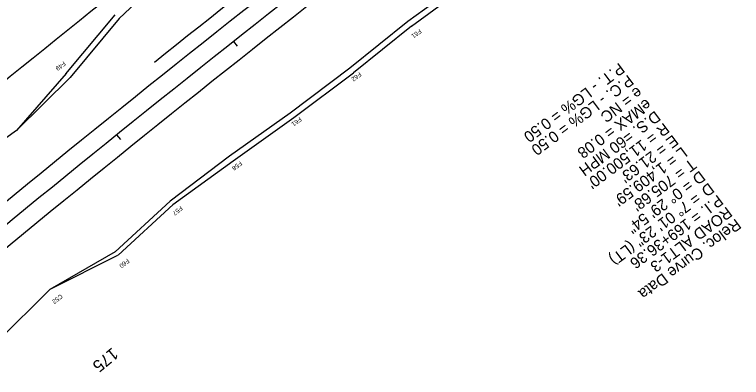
# Model space of a CAD drawing. Extents: x 1469024 to 1473560, y 1105695 to 1109739.
# Drawn here: x 1470653 to 1471138.3, y 1107228.2 to 1107470.7 of the extents above; entities that cross this region are included whole.
import ezdxf

# ---------------------------------------------------------------- set-up
doc = ezdxf.new("R2010")
doc.units = 0
for name, color, linetype in [('RD_HC_CL_Rel', 7, 'Continuous'), ('RD_HC_Data_Rel', 7, 'Continuous'), ('RD_HC_Data_Tic_Rel', 7, 'Continuous'), ('RD_HC_TX_Rel_Sta50', 7, 'Continuous'), ('RD_PD_CstnLmt', 7, 'Continuous'), ('RD_PD_CstnLmt_TX', 7, 'Continuous'), ('RD_PD_DR_ErosCtrl', 7, 'Continuous'), ('RD_PD_Final_TrvlWay', 7, 'Continuous'), ('RD_PD_GR', 7, 'Continuous'), ('RD_PD_RW', 7, 'Continuous')]:
    doc.layers.add(name, color=color, linetype=linetype)

msp = doc.modelspace()

# ---------------------------------------------------------------- linework, layer by layer
at = {"layer": 'RD_HC_CL_Rel'}
msp.add_arc((1477943.58, 1098441.09), 11500, 126.41418, 130.102414, dxfattribs=at)
at = {"layer": 'RD_HC_Data_Tic_Rel'}
for p, q in [((1470799.26, 1107452.68), (1470801.75, 1107449.55)), ((1470721.17, 1107390.22), (1470723.69, 1107387.1))]:
    msp.add_line(p, q, dxfattribs=at)
at = {"layer": 'RD_PD_CstnLmt'}
for p, q in [((1470759.49, 1107502.85), (1470722.99, 1107467.99)), ((1470955.81, 1107495.34), (1470915.62, 1107466.03)), ((1470722.99, 1107467.99), (1470690.23, 1107428.56)), ((1470915.62, 1107466.03), (1470876.9, 1107434.8)), ((1470876.9, 1107434.8), (1470837.14, 1107404.9)), ((1470690.23, 1107428.56), (1470654.32, 1107393.13)), ((1470837.14, 1107404.9), (1470796.58, 1107375.99)), ((1470654.32, 1107393.13), (1470613.1, 1107364.23)), ((1470796.58, 1107375.99), (1470756.88, 1107345.98)), ((1470756.88, 1107345.98), (1470720.21, 1107312.21)), ((1470720.21, 1107312.21), (1470676.63, 1107286.9)), ((1470676.63, 1107286.9), (1470641.02, 1107251.62))]:
    msp.add_line(p, q, dxfattribs=at)
at = {"layer": 'RD_PD_DR_ErosCtrl'}
for p, q in [((1470958.17, 1107492.11), (1470917.97, 1107462.79)), ((1470719.91, 1107470.55), (1470687.15, 1107431.12)), ((1470918.13, 1107462.91), (1470879.42, 1107431.68)), ((1470687.42, 1107431.41), (1470654.32, 1107393.13)), ((1470879.31, 1107431.6), (1470839.55, 1107401.7)), ((1470839.47, 1107401.64), (1470798.91, 1107372.73)), ((1470798.91, 1107372.73), (1470758.68, 1107343.59)), ((1470758.91, 1107343.77), (1470722.24, 1107310)), ((1470721.72, 1107309.62), (1470676.63, 1107286.9))]:
    msp.add_line(p, q, dxfattribs=at)
at = {"layer": 'RD_PD_Final_TrvlWay'}
for radius in [11512, 11488]:
    msp.add_arc((1477943.58, 1098441.09), radius, 126.41418, 130.102414, dxfattribs=at)
at = {"layer": 'RD_PD_GR'}
msp.add_arc((1477943.58, 1098441.09), 11522, 127.151906, 128.656189, dxfattribs=at)
at = {"layer": 'RD_PD_RW'}
msp.add_arc((1477943.58, 1098441.09), 11575, 126.41418, 129.547337, dxfattribs=at)

# ---------------------------------------------------------------- texts
at = {"layer": 'RD_HC_Data_Rel'}
for s, rotation, p in [('P.T. - LG% = 0.50', 216.7283, (1471056.77, 1107438.83)), ('P.C. - LG% = 0.50', 216.7283, (1471062.75, 1107430.82)), ('e = NC', 216.7283, (1471068.73, 1107422.8)), ('eMAX = 0.08', 216.7283, (1471074.71, 1107414.79)), ('D.S. =60 MPH', 216.7283, (1471080.69, 1107406.77)), ("R = 11,500.00'", 216.7689, (1471086.62, 1107398.73)), ("E = 21.63'", 216.7689, (1471092.61, 1107390.72)), ("L = 1,409.59'", 216.7689, (1471098.59, 1107382.7)), ("T = 705.68'", 216.7689, (1471104.58, 1107374.69)), ('D = 0%%d 29\' 54"', 216.7689, (1471110.57, 1107366.68)), ('D', 216.7689, (1471116.55, 1107358.67)), ('    = 7%%d 01\' 23" (LT)', 216.7689, (1471116.55, 1107358.67)), ('P.I. = 169+36.36', 216.7689, (1471122.54, 1107350.66)), ('ROAD ALT1-3', 216.7283, (1471128.53, 1107342.66)), ('Reloc. Curve Data', 216.7283, (1471134.51, 1107334.64))]:
    msp.add_text(s, height=7.5, rotation=rotation, dxfattribs=at).set_placement(p)
at = {"layer": 'RD_HC_TX_Rel_Sta50'}
msp.add_text('175', height=8, rotation=219.4035, dxfattribs=at).set_placement((1470718.2, 1107248.56))
at = {"layer": 'RD_PD_CstnLmt_TX'}
for s, rotation, p in [('F61', 216.2301, (1470923.41, 1107461.2)), ('F49', 217.2266, (1470685.76, 1107439.61)), ('F62', 216.4792, (1470883.26, 1107432.38)), ('F61', 216.7283, (1470843.32, 1107402.37)), ('F58', 216.9774, (1470803.56, 1107372.92)), ('F57', 217.2266, (1470763.85, 1107342.93)), ('F60', 217.4757, (1470728.33, 1107307.73)), ('C52', 217.7248, (1470683.79, 1107284.11))]:
    msp.add_text(s, height=3, rotation=rotation, dxfattribs=at).set_placement(p)

doc.saveas('drawing.dxf')
